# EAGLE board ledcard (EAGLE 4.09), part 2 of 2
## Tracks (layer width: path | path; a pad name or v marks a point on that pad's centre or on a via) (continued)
B$I.25  (via drill 0.2) (continued)
  Bottom 0.2: 95.08,25.39 79.29,25.39 | v95.08,25.41 95.08,25.39 | 95.08,25.39 95.12,25.39 | 58.66,26.21 52.28,32.59 52.28,32.96 52.23,33.01 49.93,33.01 49.93,32.98 v49.91,32.96
B$I.26  (via drill 0.2)
  Top 0.15: U.Y.P$P5 30.23,58.17 30.23,59.59 30.76,60.11 30.75,60.11 | U.X1.P$P5 34.35,18.01 34.35,19.18 33.53,19.99 v33.58,40.55 | U.X2.P$P5 101.53,17.99 101.53,18.79 101.19,18.79 96.64,23.29 94.7,23.29 94.43,23.56 v94.37,23.56 | 30.75,60.11 30.74,60.1 | 30.75,60.11 30.79,60.15 v32.71,60.15 33.26,60.15 36.24,57.43 36.23,57.19 45.03,48.39 v45.03,47.18 v45.02,47.18
  Top 0.2: v76.88,23.59 76.41,24.06 76.41,27.61 76.42,27.63 U2.24 | v56.83,44.86 56.83,42.88 56.49,42.54 56.49,40.51 v54.7,38.72 | v54.7,38.72 v54.69,38.71 | v54.7,38.73 v54.7,38.72 | v76.87,30.97 76.43,30.53 76.43,28.82 | U2.24 76.42,28.91 | U2.24 76.43,28.82 | 76.43,28.82 76.43,28.61
  Bottom 0.15: v33.58,40.55 33.73,40.76 33.73,45.51 | 32.7,60.15 32.69,60.15 | v32.71,60.15 32.7,60.15 | 33.63,59.34 33.51,59.34 32.7,60.15 | v54.69,38.72 54.81,38.72 58.23,35.3 58.72,35.3 58.74,35.32 58.75,35.32 | 33.63,45.76 33.63,51.12 33.64,51.12 34.92,52.4 34.92,54.32 33.74,55.5 33.74,56.25 33.68,56.31 33.68,59.18 v32.72,60.14 | 94.37,23.59 94.38,23.58 v94.38,23.57 v94.37,23.56 | 47.14,44.78 46.8,45.13 46.8,45.75 45.37,47.18 v45.03,47.18 v45.02,47.18
  Bottom 0.17: 33.63,45.76 33.73,45.51 | v54.69,38.72 v54.7,38.73
  Bottom 0.2: 94.37,23.59 v76.88,23.59 | 47.14,44.78 56.73,44.76 v56.83,44.86 | 58.75,35.32 58.99,35.56 62.01,35.56 62.12,35.45 65.53,35.45 70.1,30.88 76.79,30.88 v76.87,30.96 v76.87,30.97 | v32.72,60.14 32.72,60.13 v32.71,60.15
B$I.27  (via drill 0.2)
  Top 0.15: v34.15,39.91 33.93,39.94 | U.X2.P$P6 101.93,18.81 97.1,23.64 95.19,23.64 94.95,23.89 | 34.08,39.91 33.96,39.79 33.96,20.02 34.76,19.22 34.76,18.41 | 52.48,37.91 52.48,37.92 52.47,37.91 | 52.48,37.91 v52.47,37.9 | 79.68,26.94 79.68,26.92 80.13,26.47 81.17,26.47 | 52.48,37.91 52.47,37.91 | 52.47,37.91 v52.45,37.89 | 52.48,37.9 52.48,37.89 | 52.48,37.9 52.48,37.91 | 52.48,37.9 52.47,37.91 | 52.48,37.91 52.45,37.91 52.44,37.9 52.45,37.9 | 52.45,37.9 52.48,37.9 | U.Y.P$P6 31.1,58.24 31.63,58.24 | 31.63,58.24 31.62,58.25 31.76,58.39 v34.27,58.39 | 31.63,58.24 31.65,58.24 | v52.46,37.89 v52.45,37.88 52.43,37.88 52.45,37.9
  Top 0.17: v34.15,39.91 34.08,39.91 34.81,39.91 35.01,39.71 46.11,39.71 47.88,37.94 52.46,37.94 52.48,37.92 | U.Y.P$P6 | 55.96,45.51 61.03,45.51 62.29,44 69.5,44 70.83,45.33 70.85,45.31 71.31,45.31 | 52.48,37.92 52.48,37.91 | 52.48,37.92 52.46,37.92
  Top 0.2: U2.64 72.92,43.69 71.31,45.31 | 55.96,45.51 55.93,45.26 55.93,41.47 52.36,37.9 | 94.95,23.89 92.33,26.47 81.17,26.47 | 79.68,26.94 79.68,27.41 v79.51,27.59 | 52.36,37.9 52.35,37.89 | 52.46,37.92 52.36,37.9 | U.X1.P$P6 34.76,18.41
  Bottom 0.15: v34.15,39.91 34.16,40.11 34.16,48.21 34.11,48.26 34.11,51.01 34.12,51.01 35.23,52.12 35.23,54.5 34.08,55.65 34.08,58.2 v34.27,58.39 | 64.41,29.19 63.52,29.19 54.77,37.93 52.5,37.93 52.48,37.91 | 52.48,37.91 v52.46,37.89 | 52.48,37.91 52.48,37.92
  Bottom 0.2: v79.51,27.59 77.76,29.34 64.53,29.31 64.41,29.19
B$I.28  (via drill 0.2, 0.3)
  Top 0.15: U.X1.P$R5 33.56,17.99 33.56,18.89 32.53,19.91 v32.51,41.96 | 29.43,58.95 U.Y.P$R5 29.43,58.97 29.43,60.56 30.21,61.34 v31.04,61.34 | v32.51,41.96 v32.51,41.98 | U.X2.P$R5 100.74,17.99 99.43,17.99 97.88,19.54 | 56.18,38.95 v54.06,36.83 v54.05,36.83 | 33.73,42.11 32.59,42.11 v32.51,41.96
  Top 0.17: v51.31,39.44 50.56,38.69 48.31,38.69 46.58,40.41 35.43,40.41 33.73,42.11
  Top 0.2: 97.88,19.54 97.73,19.69 72.83,19.69 | v60.33,29.09 61.03,28.39 61.03,27.71 69.06,19.69 72.83,19.69 | 72.83,19.69 72.71,19.69 | 56.18,38.95 57.13,39.9 v57.13,42.12 | U2.60 74.93,41.61 v75.53,42.14
  Bottom 0.15: v60.33,29.09 60.33,31.71 55.21,36.83 v54.05,36.83 | v32.51,41.98 32.53,41.91 32.76,42.14 32.91,42.1 32.91,51.41 32.91,51.4 32.92,51.4 32.92,51.56 34.25,52.89 34.25,54.06 32.94,55.37 32.94,55.62 31.38,57.18 31.38,57.39 | 52.31,42.2 52.31,42.26 56.99,42.26 v57.13,42.12
  Bottom 0.17: v31.04,61.34 31.38,60.84 31.38,57.39
  Bottom 0.2: v51.31,39.44 52.31,42.2 75.53,42.22 v75.53,42.14
B$I.29  (via drill 0.2)
  Top 0.15: U.X1.P$R6 33.96,19.08 33.01,20.04 33.01,41.41 33.03,41.39 v33.13,41.49 33.81,41.49 | U.X2.P$R6 100.95,18.39 100.28,19.06 100.07,19.06 96.23,22.9 94.03,22.9 94.03,22.91 94.04,22.91
  Top 0.17: 51.53,38.36 48.03,38.36 46.36,40.04 35.26,40.04 33.81,41.49 | U.Y.P$R6 v32.73,59.15
  Top 0.2: v92.51,24.44 94.04,22.91 | 51.53,38.36 51.95,38.36 54.96,41.37 54.96,45.26 55.79,46.09 61.14,46.09 62.74,44.49 69,44.49 69.57,45.06 v69.58,45.1 | v77.29,44.39 76.92,44.18 U2.56 | U2.56 76.93,40.43 | v76.93,38.52 U2.56
  Bottom 0.15: 33.26,41.66 33.13,41.53 v33.13,41.49 | 33.26,58.24 33.26,56.12 33.39,55.98 33.39,55.42 34.58,54.23 34.58,52.61 33.27,51.3 33.27,51.29 33.26,51.29 33.26,50.2 33.25,50.19 33.26,50.19
  Bottom 0.17: 33.26,41.66 33.26,50.19
  Bottom 0.2: v92.51,24.44 97.21,24.44 98.53,25.76 98.53,27.16 93.65,32.03 93.62,32.05 93.62,32.06 83.37,32.06 v76.93,38.52 | v69.58,45.1 71.1,45.1 71.74,44.32 77.28,44.32 v77.29,44.39 | v32.73,59.15 32.98,58.51 33.26,58.24
B$I.30  (via drill 0.2)
  Top 0.15: U.Y.P$T6 31.92,59.36 | U.X1.P$T6 31.96,19.59 31.96,40.66 31.93,40.64 31.91,40.66 31.93,40.66 31.94,40.72 | 32.83,43.21 32.82,43.2 32.63,43.2 v31.99,43.84 | v96.21,22.1 v96.22,22.1 99.92,18.39 U.X2.P$T6
  Top 0.17: v50.26,39.34 48.36,39.34 46.86,40.84 35.73,40.84 33.36,43.21 32.83,43.21 31.94,42.27 31.94,40.72 | v31.94,59.59 31.92,59.36
  Top 0.2: v78.41,38.34 78.68,38.6 78.68,38.89 78.91,39.1 78.92,39.11 U2.52 | v78.78,43.76 v78.77,43.75 78.78,43.74 78.78,43.73 78.92,43.59 U2.52 | U2.52
  Bottom 0.15: 32.57,55.51 32.57,55.3 33.93,53.83 33.93,53.03 31.99,51.13 v31.99,43.84
  Bottom 0.17: 32.57,55.51 30.91,57.19 30.91,60.68 30.18,61.41 30.18,61.81 30.33,61.96 31.38,61.96 31.83,61.51 31.83,60.01 v31.94,59.59
  Bottom 0.2: v78.78,43.76 78.58,42.64 78.16,42.21 76.71,42.21 76.11,42.81 51.63,42.79 v50.26,39.34 | v96.22,22.1 99.18,25.06 99.18,27.29 93.86,32.61 84.05,32.61 78.89,37.77 78.91,37.79 v78.41,38.34
B$I.31  (via drill 0.2)
  Top 0.15: U.X1.P$T5 31.36,19.39 v31.36,31.99 v31.36,41.14 | U.Y.P$T5 29.81,59.37 29.81,60.14 30.18,60.59 v30.19,60.56 | U.X2.P$T5 98.95,17.59 v98.28,18.26 | 39.41,31.76 39.09,31.76 v38.84,31.51
  Top 0.17: v50.78,31.76 39.41,31.76
  Top 0.2: 74.42,24.79 U2.20 | v74.42,24.08 74.42,24.79 | 74.42,24.79 74.43,24.79 74.43,24.16
  Bottom 0.15: 37.58,30.54 37.58,30.55 37.57,30.55 38.53,31.51 v38.84,31.51 | 30.18,55.71 31.9,53.99 33.35,53.99 33.35,53.98 33.61,53.72 33.61,53.16 33.1,52.65 32.15,52.64 31.41,51.92 31.43,51.91
  Bottom 0.17: v31.36,41.14 31.43,51.91 | 30.18,55.71 v30.19,60.56 | 37.58,30.54 32.76,30.54 31.62,31.68
  Bottom 0.2: v50.78,31.76 58.13,24.56 74.08,24.56 74.43,24.21 74.43,24.07 | 31.62,31.68 31.38,31.94 31.34,31.97 v31.36,31.99 | v98.28,18.26 97.38,18.26 94.24,21.4 75.24,21.4 74.43,22.21 74.43,24.07 | 74.43,24.07 v74.42,24.08
B$USB.D+  (via drill 0.2)
  Top 0.17: U3.P$4 91.18,53.54 92.28,53.54 v92.51,53.31
  Top 0.2: K1.P$D- 126.5,88.75 v96.33,58.59
  Bottom 0.17: v96.33,58.59 92.51,54.76 v92.51,53.31
B$USB.D-  (via drill 0.2)
  Top 0.17: U3.P$5 93.15,54.01 v93.21,53.96
  Top 0.2: K1.P$D+ 124.46,84.94 v97.86,58.34
  Bottom 0.17: v93.21,53.96 93.21,54.26 96.76,57.81 97.33,57.81 v97.86,58.34
B$USB.VBUS
  Top 0.17: U3.P$7 91.16,55.76 91.88,55.76 U3.P$8 91.94,55.76 91.94,56.59 93.16,57.81 93.16,59.29 93.21,59.34 91.86,60.69 91.91,60.74 U1.1 93.38,62.26 93.38,63.71 C2.P | 147.18,92.44 147.18,92.47 K1.P$VCC
  Top 0.2: C2.P 122.05,92.44 147.18,92.44
B$X.I.CP  (via drill 0.2)
  Top 0.15: 58.48,25.25 58.48,25.26 | 58.48,25.24 58.48,14.41 | v39.83,12.3 v39.83,12.31 39.81,12.32 39.96,12.47 39.96,16.31 39.59,16.68 39.59,16.79 U.X1.P$H4 39.55,16.78 U.X1.P$J4 | U.X1.P$A4 45.16,16.77 45.6,16.34 v46.13,16.34
  Top 0.2: 58.48,14.41 v55.93,11.75 | v46.13,16.34 46.18,16.29 46.18,16.26 | U.X1.P$T4 33.15,16.8 32.32,16.8 v32.31,16.81 | v75.37,25.19 75.36,25.19 75.33,25.22 75.42,25.31 U2.22 | 58.48,25.24 58.48,25.25 58.48,25.19 v58.51,25.16
  Bottom 0.15: 46.16,16.31 43.36,16.31 v39.83,12.3 39.83,12.74 | v58.51,25.16 75.35,25.19 75.35,25.18 | 75.35,25.18 75.34,25.17 | v75.37,25.19 75.35,25.18 | 39.83,12.74 39.84,12.72 | 35.88,13.24 39.33,13.24 39.83,12.74 | v55.93,11.75 v55.93,11.76 55.26,11.09
  Bottom 0.2: 35.88,13.24 v32.31,16.81 | 46.16,16.31 51.38,11.09 55.26,11.09 | 46.16,16.31 v46.13,16.34 | 46.16,16.31 46.18,16.29 46.18,16.26
B$X.I.CP.1  (via drill 0.2)
  Top 0.15: U.X2.P$A4 v113.41,17.09 | v99.61,16.75 U.X2.P$T4 | 77.76,24.86 77.76,24.79 89.57,24.79 | 107.16,13.71 107.12,13.78 107.12,16.6 106.93,16.6 U.X2.P$H4 106.72,16.78 105.92,16.78 | 105.92,16.78 105.9,16.78 | 105.92,16.78 U.X2.P$J4
  Top 0.2: U2.26 77.42,25.95 77.42,25.4 77.42,25.17 77.76,24.86 | v93.92,20.49 89.57,24.79 | 107.16,13.69 107.16,13.71 | 107.16,13.69 107.16,13.66 107.16,13.65 | 107.16,13.64 v107.16,12.29 | 107.16,13.64 107.16,13.69 | 107.16,13.64 107.14,13.62
  Bottom 0.15: 99.61,16.74 99.6,16.73 | v99.61,16.76 99.61,16.74 | v99.61,16.75 99.64,16.77 99.61,16.74 | 107.18,13.67 107.18,13.69 107.17,13.7 108.56,15.09 | 108.56,15.11 108.56,15.09 | 105.53,15.31 108.38,15.31 108.6,15.09 | 108.6,15.09 108.58,15.09 | 108.6,15.09 108.5,15.19 108.47,15.19 108.47,15.18 108.56,15.09
  Bottom 0.2: 98.83,16.76 v99.61,16.76 | 98.83,16.76 98.26,16.19 98.26,15.74 98.68,15.31 105.53,15.31 | v93.92,20.49 93.91,20.49 93.9,20.48 97.62,16.76 98.83,16.76 | 107.18,13.67 107.16,13.69 | 107.16,13.69 v107.16,12.29 107.16,13.62 | 107.16,13.62 107.17,13.61 | 107.16,13.69 107.16,13.63 107.16,13.62 | v113.41,17.09 113.73,16.76 113.73,16.66 113.88,16.51 113.88,15.31 113.68,15.11 108.56,15.11
B$X.O.0
  Top 0.15: U.X1.P$A2 45.95,15.19 52.21,8.93 68.01,8.93 74.71,2.23 | X.0.P$ 74.71,2.23 | 74.71,2.23 74.72,2.23
B$X.O.1
  Top 0.15: U.X1.P$A1 52.08,7.44 64.87,7.44 70.08,2.26 70.07,2.25 X.1.P$
B$X.O.2
  Top 0.15: U.X1.P$B2 44.76,14.79 45.53,14.79 52.05,8.27 66.5,8.27 72.46,2.31 72.41,2.26 72.38,2.26 72.37,2.25 X.2.P$
B$X.O.3
  Top 0.15: U.X1.P$B1 51.89,6.86 63.11,6.86 67.78,2.19 X.3.P$
B$X.O.4
  Top 0.15: U.X1.P$C2 43.96,14.79 43.96,14 51.85,6.14 61.66,6.14 65.5,2.29 | X.4.P$ 65.48,2.29 65.5,2.29 | 65.5,2.29 65.51,2.27
B$X.O.5
  Top 0.15: U.X1.P$C1 43.56,13.89 51.89,5.49 59.91,5.49 X.5.P$ | X.5.P$ 63.21,2.21 | X.5.P$ | X.5.P$ | X.5.P$
B$X.O.6
  Top 0.15: U.X1.P$D2 43.16,14.79 43.16,13.79 52.02,4.92 58.23,4.92 60.93,2.23 60.93,2.22 | 60.93,2.22 60.93,2.21 | X.6.P$ 60.93,2.22
B$X.O.7
  Top 0.15: U.X1.P$D1 42.76,13.59 52.1,4.24 56.6,4.24 X.7.P$ | X.7.P$ 58.59,2.22 X.7.P$ | X.7.P$ 58.63,2.21
B$X.O.8
  Top 0.15: U.X1.P$J2 38.36,14.79 38.36,13.14 35.66,10.44 X.8.P$
B$X.O.9
  Top 0.15: X.9.P$ 37.98,2.21 37.98,12.24 38.76,13.01 U.X1.P$J1 | U.X1.P$J1 | U.X1.P$J1
B$X.O.10
  Top 0.15: U.X1.P$K2 37.56,14.79 37.56,13.31 31.16,6.91 31.16,2.29 X.10.P$
B$X.O.11
  Top 0.15: U.X1.P$K1 37.96,13.26 33.38,8.69 33.38,2.24 X.11.P$
B$X.O.12
  Top 0.15: U.X1.P$L2 36.75,14.79 36.75,13.54 26.53,3.32 26.53,2.16 26.51,2.14 26.53,2.11 | 26.53,2.11 26.56,2.09 | 26.53,2.11 X.12.P$
B$X.O.13
  Top 0.15: X.13.P$ 28.89,2.22 28.93,2.26 28.78,2.41 28.77,2.4 | U.X1.P$L1 37.16,13.38 28.77,4.99 28.77,2.4 | 28.77,2.4 28.77,2.26
B$X.O.14
  Top 0.15: U.X1.P$M2 35.96,14.79 35.96,13.74 33.33,11.11 29.22,11.11 | X.14.P$ 22.01,2.24 22.01,3.89 29.22,11.09 29.22,11.11 | 29.22,11.11 29.22,11.12
B$X.O.15
  Top 0.15: X.15.P$ 24.22,2.24 24.16,2.31 24.18,2.34 24.18,3.85 | U.X1.P$M1 36.36,13.65 32.83,10.12 30.38,10.12 24.18,3.92 24.18,3.85 | 24.18,3.85 24.18,3.91
B$X.O.16
  Top 0.15: U.X1.P$E2 42.36,14.79 42.36,13.33 51.9,3.79 54.75,3.79 56.29,2.24 56.29,2.23 X.16.P$
B$X.O.17
  Top 0.15: U.X1.P$E1 41.96,13.11 52.11,3.07 53.18,3.07 54.01,2.24 X.17.P$
B$X.O.18
  Top 0.15: U.X1.P$F2 41.56,14.79 41.56,12.56 51.73,2.38 51.73,2.21 | 51.73,2.21 51.73,2.19 | 51.73,2.21 X.18.P$
B$X.O.19
  Top 0.15: U.X1.P$F1 41.16,13.61 41.16,12.01 49.41,3.7 49.41,2.25 49.45,2.26 X.19.P$
B$X.O.20
  Top 0.15: U.X1.P$G2 40.76,14.79 40.76,11.17 47.13,4.79 47.13,2.21 X.20.P$
B$X.O.21
  Top 0.15: X.21.P$ 44.86,2.21 44.86,5.74 44.87,5.72 | U.X1.P$G1 40.42,14.33 40.42,10.89 44.87,6.44 44.87,5.72 | 44.87,5.72 44.87,5.68
B$X.O.22
  Top 0.15: U.X1.P$H1 39.56,12.88 39.07,12.39 39.07,9.65 42.39,6.33 42.51,6.33 42.51,6.34 42.53,6.36 X.22.P$
B$X.O.23
  Top 0.15: X.23.P$ 40.26,2.26 38.31,4.21 38.31,12.13 39.09,12.91 39.09,12.98 39.14,12.98 39.15,12.97 39.15,14.78 U.X1.P$H2
B$X.O.24
  Top 0.15: U.X1.P$N2 35.16,14.79 35.16,13.84 33.56,12.24 27.48,12.24 | X.24.P$ 17.45,2.22 17.46,2.21 27.48,12.26 27.48,12.24 | 27.48,12.24 27.51,12.25
B$X.O.25
  Top 0.15: X.25.P$ 19.63,2.26 29.09,11.71 | U.X1.P$N1 35.56,13.79 33.5,11.72 29.09,11.71 | 29.11,11.69 29.07,11.65 29.09,11.71
B$X.O.26
  Top 0.15: U.X1.P$P2 34.36,14.79 34.36,14.09 33.63,13.36 24.04,13.36 X.26.P$ | X.26.P$ | 12.92,2.22 X.26.P$ | 12.92,2.22 X.26.P$ | 12.92,2.22
B$X.O.27
  Top 0.15: U.X1.P$P1 34.76,13.88 33.54,12.66 25.57,12.66 X.27.P$ | X.27.P$ | X.27.P$
B$X.O.28
  Top 0.15: X.28.P$ 8.11,4.31 10.58,4.31 21.06,14.79 21.07,14.78 | 21.07,14.78 21.02,14.77 | U.X1.P$R2 33.57,14.78 21.07,14.78
B$X.O.29
  Top 0.15: U.X1.P$R1 33.48,13.91 22.23,13.91 X.29.P$ | X.29.P$ 10.55,2.14 | X.29.P$
B$X.O.30
  Top 0.15: U.X1.P$T1 21.6,14.39 | 21.6,14.39 21.58,14.41 | 21.6,14.39 10.8,3.59 9.63,3.59 8.36,2.31 8.18,2.31 | 8.18,2.31 8.13,2.31 | 8.18,2.31 X.30.P$
B$X.O.31
  Top 0.15: U.X1.P$T2 19.61,15.19 9.43,5.01 6.36,5.01 3.71,2.36 3.72,2.35 X.31.P$
B$X.O.32
  Top 0.15: X.32.P$ 132.8,15.19 U.X2.P$A2
B$X.O.33
  Top 0.15: 131.37,14.39 U.X2.P$A1
  Top 0.2: X.33.P$ 141.23,2.21 141.23,4.54 131.37,14.39
B$X.O.34
  Top 0.15: U.X2.P$B2 111.94,15.59 134.75,15.59 X.34.P$
B$X.O.35
  Top 0.15: X.35.P$ 138.95,2.16 138.96,2.16 138.96,3.24 131.61,10.59 116.53,10.59 116.57,10.55 | U.X2.P$B1 112.07,13.85 113.2,13.85 116.5,10.55 116.57,10.55 | 116.57,10.55 116.59,10.55
B$X.O.36
  Top 0.15: U.X2.P$C2 111.14,14.79 131.93,14.81 143.41,3.34 143.41,2.26 143.44,2.26 X.36.P$
B$X.O.37
  Top 0.15: X.37.P$ 136.52,2.29 136.51,2.29 136.51,2.86 129.21,10.16 116.02,10.16 115.98,10.2 115.96,10.2 115.96,10.64 113.08,13.53 111.6,13.53 U.X2.P$C1
B$X.O.38
  Top 0.15: U.X2.P$D2 110.33,14.81 110.33,14.03 111.18,13.17 112.87,13.17 115.63,10.41 115.63,10.06 115.98,9.71 115.98,9.6 116,9.59 126.98,9.59 134.26,2.31 134.26,2.18 | 134.26,2.18 134.26,2.16 | X.38.P$ 134.26,2.18
B$X.O.39
  Top 0.15: U.X2.P$D1 109.93,13.96 111.07,12.82 112.64,12.82 115.28,10.18 115.28,9.85 115.63,9.5 115.63,9.26 115.96,8.94 116.27,8.94 | X.39.P$ 132.03,2.24 125.33,8.94 116.27,8.94 | 116.27,8.94 116.31,8.94 | 116.27,8.94
B$X.O.40
  Top 0.15: U.X2.P$J2 105.53,14.79 105.53,12.7 104.44,11.61 104.44,7.81 105.54,6.71 105.54,5.89 105.49,5.84 105.53,5.8 105.53,5.76 | 109.05,2.25 X.40.P$
  Top 0.2: 105.53,5.76 109.05,2.25
B$X.O.41
  Top 0.15: U.X2.P$J1 105.93,12.63 104.86,11.56 104.86,8 109.43,3.43 110.15,3.43 111.3,2.29 111.39,2.29 111.39,2.25 X.41.P$
B$X.O.42
  Top 0.15: U.X2.P$K2 104.73,14.79 104.73,12.88 103.5,11.65 103.5,7.2 104.47,6.24 104.48,6.24 | 104.48,2.26 104.48,2.25 104.5,2.23 104.49,2.22 X.42.P$
  Top 0.2: 104.48,6.24 104.48,2.26
B$X.O.43
  Top 0.15: 106.78,2.26 106.77,2.25 X.43.P$ | 105.14,3.9 105.14,6.45 104.02,7.58 104.04,7.58 | U.X2.P$K1 105.13,12.81 104.02,11.7 104.02,7.6 104.04,7.58 | 104.04,7.58 104.06,7.55
  Top 0.2: 105.13,3.91 105.14,3.9 106.78,2.26
B$X.O.44
  Top 0.15: U.X2.P$L2 103.93,14.79 103.93,13.11 99.9,9.08 99.9,2.21 99.89,2.21 | X.44.P$ | X.44.P$ | 99.89,2.21 99.87,2.19 | 99.89,2.21 X.44.P$
B$X.O.45
  Top 0.15: 102.21,2.34 102.21,2.33 102.17,2.29 X.45.P$ | U.X2.P$L1 104.33,12.95 102.21,10.83 102.21,5.89 102.21,5.88 | 102.21,5.88 102.19,5.87 | 102.21,5.88 102.21,5.89
  Top 0.2: 102.21,5.89 102.21,2.34
B$X.O.46
  Top 0.15: U.X2.P$M2 103.13,14.79 103.13,13.46 95.31,5.63 95.31,2.99 95.33,3.01 95.33,3.04 | 95.33,2.25 95.28,2.25 95.27,2.24 95.29,2.22 X.46.P$
  Top 0.2: 95.33,3.04 95.33,2.25
B$X.O.47
  Top 0.15: X.47.P$ | U.X2.P$M1 103.53,13.3 97.58,7.34 97.58,3.78 97.53,3.74 97.58,3.69 | 97.58,3.69
  Top 0.2: 97.58,3.69 X.47.P$
B$X.O.48
  Top 0.15: U.X2.P$E2 109.53,14.79 109.53,13.47 110.67,12.33 112.31,12.33 115.3,9.33 115.3,9.01 116.17,8.14 116.24,8.14 116.17,8.21 116.15,8.21 | X.48.P$ 129.8,2.23 129.81,2.24 123.91,8.14 116.23,8.14 116.15,8.21 | 116.15,8.21 116.1,8.21
B$X.O.49
  Top 0.15: X.49.P$ 127.43,2.29 122.08,7.64 116.16,7.61 116.17,7.6 | U.X2.P$E1 109.13,13.4 110.55,11.98 112.17,11.98 114.91,9.24 114.91,8.8 116.03,7.67 116.03,7.6 116.17,7.6 | 116.17,7.6 116.26,7.6
B$X.O.50
  Top 0.15: U.X2.P$F2 108.73,14.79 108.73,13.29 110.44,11.58 111.77,11.58 114.56,8.8 114.56,8.44 116.64,6.36 121.14,6.36 125.16,2.33 125.13,2.3 X.50.P$
B$X.O.51
  Top 0.15: U.X2.P$F1 108.36,14.37 108.36,13.12 110.27,11.21 111.51,11.21 114.23,8.49 114.23,8.12 117.83,4.51 117.88,4.51 | X.51.P$ 122.86,2.26 120.56,4.56 120.55,4.55 120.55,4.51 117.88,4.51 | 117.88,4.51 117.83,4.51
B$X.O.52
  Top 0.15: X.52.P$ 120.54,2.24 120.55,2.23 | U.X2.P$G2 107.53,15.17 107.92,14.8 107.92,14.21 108.04,14.07 108.04,12.97 110.11,10.9 110.97,10.9 111.58,10.29 111.58,10.22 116.99,4.81 116.99,4.74 117.95,3.78 117.98,3.81 120.01,3.81 120.55,3.27 120.55,2.23 | 120.55,2.23 X.52.P$
B$X.O.53
  Top 0.15: 118.24,2.25 X.53.P$ | U.X2.P$G1 107.53,14.12 107.68,13.96 107.68,12.79 118.22,2.25 118.24,2.25 | 118.26,2.24 118.25,2.24 118.24,2.25
B$X.O.54
  Top 0.15: U.X2.P$H1 106.64,14.33 106.64,12.43 105.73,11.51 105.73,8.3 109.61,4.42 113.76,4.42 115.94,2.24 115.63,2.24 | 115.91,2.24 X.54.P$
  Top 0.2: 115.63,2.24 115.91,2.24
B$X.O.55
  Top 0.15: U.X2.P$H2 106.33,14.79 106.33,12.56 105.28,11.51 105.28,8.19 109.52,3.95 112.03,3.95 113.65,2.32 X.55.P$ | X.55.P$ 113.68,2.19 | X.55.P$
B$X.O.56
  Top 0.15: U.X2.P$N2 102.33,14.79 102.33,13.88 101.28,12.82 101.28,12.8 100.11,11.63 100.11,11.61 | 90.73,2.24 X.56.P$
  Top 0.2: 100.11,11.61 90.73,2.24
B$X.O.57
  Top 0.15: X.57.P$ 92.96,2.26 93.01,2.26 93.01,3.95 102.73,13.67 U.X2.P$N1
B$X.O.58
  Top 0.15: U.X2.P$P2 101.53,14.79 101.53,14.06 101,13.53 97.46,13.53 97.07,13.14 | X.58.P$ | 97.07,13.14 97.04,13.1 | 97.07,13.14 97.08,13.14
  Top 0.2: 97.08,13.14 X.58.P$
B$X.O.59
  Top 0.15: 88.38,2.26 X.59.P$ | U.X2.P$P1 101.93,13.95 101.16,13.17 99.33,13.17 98.89,12.74 98.88,12.74
  Top 0.2: 98.88,12.74 88.38,2.26
B$X.O.60
  Top 0.15: U.X2.P$R2 100.73,14.79 100.66,14.8 91.78,14.81 | X.60.P$ 79.27,2.22 79.27,2.23 79.23,2.26
  Top 0.2: 91.78,14.81 79.23,2.26
B$X.O.61
  Top 0.15: 83.73,2.24 83.75,2.21 X.61.P$ | U.X2.P$R1 101.13,14.22 100.81,13.9 95.45,13.9 95.26,13.71 | 95.26,13.71 95.19,13.64 | 95.26,13.71
  Top 0.2: 95.26,13.71 83.73,2.24
B$X.O.62
  Top 0.15: 81.55,2.25 X.62.P$ | U.X2.P$T1 93.69,14.39
  Top 0.2: 93.69,14.39 81.55,2.25
B$X.O.63
  Top 0.15: U.X2.P$T2 100.4,15.24 | 76.93,2.24 X.63.P$
  Top 0.2: 100.4,15.24 89.95,15.23 76.93,2.24
B$Y.I.CP  (via drill 0.2)
  Top 0.15: 29.03,53.75 U.Y.P$J4 U.Y.P$H4 29.42,53.36 31.2,53.36 | U.Y.P$A4 29.03,47.35 29.03,46.71 29.05,46.69 29.05,46.66 v29.06,46.66 v29.07,46.67 | U.Y.P$T4 29.02,60.3 v29.03,60.91 | 31.2,53.36 31.76,53.36 | v33.03,53.36 31.2,53.36
  Top 0.17: v51.61,32.41 39.83,32.41 v38.58,33.69
  Top 0.2: U2.27 77.92,25.68 v78.3,25.43
  Bottom 0.15: v38.58,33.69 38.48,33.51 | 31.76,53.36 v33.03,53.36 | 29.43,46.66 29.42,46.67 v29.07,46.67 29.03,46.71
  Bottom 0.2: 29.03,46.71 29.03,50.96 31.76,53.36 29.03,55.76 v29.03,60.91 | v51.61,32.41 58.26,25.81 58.96,25.81 58.96,25.76 77.97,25.76 v78.3,25.43 | 38.48,33.51 37.36,32.39 30.41,39.34 30.41,45.69 29.43,46.66
B$Y.O.0
  Top 0.15: 9.19,6.46 9.18,6.46 | 9.19,6.46 27.38,24.66 27.38,47.36 U.Y.P$A2 | R.0.P$1 9.19,6.46 | R.0.P$1 | R.0.P$1
B$Y.O.1
  Top 0.15: U.Y.P$A1 26.62,30.1 9.16,12.64 9.17,12.63 9.18,12.63 9.19,12.64 R.1.P$1
B$Y.O.2
  Top 0.15: U.Y.P$B2 27.02,47.76 27.02,27.22 9.33,9.54 9.14,9.54 | 9.14,9.54 9.13,9.54 | R.2.P$1 9.14,9.54
B$Y.O.3
  Top 0.15: U.Y.P$B1 26.48,48.16 25.83,47.51 25.83,32.44 9.2,15.8 R.3.P$1
B$Y.O.4
  Top 0.15: U.Y.P$C2 27.1,48.59 27.07,48.56 25.77,48.56 24.78,47.57 24.78,34.34 R.4.P$1
B$Y.O.5
  Top 0.15: U.Y.P$C1 25.28,48.96 23.81,47.49 23.81,36.61 9.21,22.01 9.16,22.01 9.16,21.98 R.5.P$1
B$Y.O.6
  Top 0.15: U.Y.P$D2 27,50.16 23.06,50.16 22.38,49.46 22.38,41.36 9.18,28.16
  Top 0.2: R.6.P$1 9.18,28.12 9.18,28.16
B$Y.O.7
  Top 0.15: U.Y.P$D1 23.78,49.76 23.08,49.06 23.08,38.96 9.18,25.06 R.7.P$1
B$Y.O.8
  Top 0.15: U.Y.P$J2 27.02,54.16 18.18,54.16 13.28,59.06 R.8.P$1 | R.8.P$1 9.18,59.06 | R.8.P$1
B$Y.O.9
  Top 0.15: U.Y.P$J1 17.48,53.76 15.28,55.96 9.18,55.96 R.9.P$1
B$Y.O.10
  Top 0.15: U.Y.P$K2 27.02,54.96 19.58,54.96 9.48,65.06 9.28,65.06 9.28,65.16 9.22,65.22 R.10.P$1
B$Y.O.11
  Top 0.15: U.Y.P$K1 26.52,54.56 18.88,54.56 11.18,62.26 9.11,62.26 | 9.11,62.26 9.08,62.26 | 9.11,62.26 R.11.P$1
B$Y.O.12
  Top 0.15: U.Y.P$L2 27.02,55.76 20.98,55.76 20.28,56.46 20.28,60.26 9.18,71.36 9.19,71.37 R.12.P$1
B$Y.O.13
  Top 0.15: U.Y.P$L1 20.28,55.36 19.58,56.06 19.58,58.06 9.2,68.44 | 9.2,68.44 9.18,68.46 | 9.2,68.44 R.13.P$1
B$Y.O.14
  Top 0.15: U.Y.P$M2 27.02,56.56 22.38,56.56 21.68,57.26 21.68,65.16 9.19,77.66 | 9.19,77.66 9.18,77.66 | R.14.P$1 9.19,77.66
B$Y.O.15
  Top 0.15: U.Y.P$M1 21.68,56.16 20.98,56.86 20.98,62.76 R.15.P$1 | R.15.P$1 | R.15.P$1
B$Y.O.16
  Top 0.15: U.Y.P$E2 26.99,50.97 21.65,50.97 20.98,50.26 20.98,46.06 9.19,34.26 | 9.19,34.26 9.18,34.26 | 9.19,34.26 R.16.P$1
B$Y.O.17
  Top 0.15: U.Y.P$E1 22.38,50.56 21.68,49.86 21.68,43.66 9.22,31.19 | 9.22,31.19 9.18,31.16 | 9.22,31.19 R.17.P$1
B$Y.O.18
  Top 0.15: U.Y.P$F2 27.01,51.76 20.29,51.77 9.28,40.76 9.28,40.46 R.18.P$1
B$Y.O.19
  Top 0.15: U.Y.P$F1 20.98,51.36 20.08,50.46 20.08,48.26 9.28,37.46 9.18,37.46 9.28,37.36
  Top 0.2: R.19.P$1 9.21,37.38 9.23,37.36 9.28,37.36
B$Y.O.20
  Top 0.15: U.Y.P$G2 27.02,52.56 18.88,52.56 12.98,46.66 9.2,46.66 | 9.2,46.66 9.18,46.66 | 9.2,46.66 R.20.P$1
B$Y.O.21
  Top 0.15: U.Y.P$G1 19.58,52.16 10.98,43.56 9.85,43.56 | 9.85,43.56 9.18,43.56 | 9.85,43.56 R.21.P$1
B$Y.O.22
  Top 0.15: U.Y.P$H1 26.22,52.96 18.18,52.96 14.98,49.76 9.97,49.76 | 9.97,49.76 9.18,49.76 | 9.97,49.76 R.22.P$1
B$Y.O.23
  Top 0.15: U.Y.P$H2 27.02,53.36 17.48,53.36 16.78,52.66 9.18,52.66 9.18,52.87 R.23.P$1
B$Y.O.24
  Top 0.15: U.Y.P$N2 27.02,57.36 23.78,57.36 23.08,58.06 23.08,70.06 9.21,83.94 | 9.21,83.94 9.08,84.06 | R.24.P$1 9.21,83.94
B$Y.O.25
  Top 0.15: U.Y.P$N1 23.08,56.96 22.38,57.66 | 9.19,80.75 9.18,80.76 | R.25.P$1 9.19,80.75 | 9.19,80.75 22.38,67.56
  Top 0.2: 22.38,67.56 22.38,57.66
B$Y.O.26
  Top 0.15: U.Y.P$P2 27.02,58.16 25.18,58.16 24.48,58.86 24.48,74.76 9.44,89.8 R.26.P$1
B$Y.O.27
  Top 0.15: U.Y.P$P1 24.48,57.76 23.78,58.46 23.78,72.36 9.18,86.96
  Top 0.2: R.27.P$1 9.18,86.96
B$Y.O.28
  Top 0.15: U.Y.P$R2 27.02,58.96 26.18,58.96 25.88,59.26 25.88,79.46 9.08,96.26 9.1,96.28 R.28.P$1
B$Y.O.29
  Top 0.15: U.Y.P$R1 25.78,58.56 25.18,59.16 25.18,77.26 9.22,93.23 | 9.22,93.23 9.18,93.26 | R.29.P$1 9.22,93.23
B$Y.O.30
  Top 0.15: U.Y.P$T1 26.62,60.42 26.63,60.46 26.63,81.96 9.34,99.24
  Top 0.2: R.30.P$1 9.34,99.24
B$Y.O.31
  Top 0.15: U.Y.P$T2 27.42,60.42 27.43,60.46 27.43,84.36 9.21,102.53 | 9.21,102.53 9.18,102.56 | R.31.P$1 9.21,102.53
GND  (via drill 0.2, 0.3)
  Top 0.15: U.Y.P$R4 | U.Y.P$R4 | U.Y.P$R4 U.Y.P$R3 29.08,58.56 29.43,58.21 29.43,57.21 29.18,56.96 U.Y.P$N3 | U.Y.P$M4 | U.Y.P$M4 U.Y.P$M3 | 28.22,56.94 U.Y.P$M3 | 27.83,52.54 27.83,54.17 U.Y.P$K3 28.2,54.56 | 27.83,52.54 27.83,52.51 28.18,52.16 | U.Y.P$D4 29.03,50.12 | U.Y.P$E4 29.03,50.55 29.03,50.12 | U.Y.P$M3 U.Y.P$N3 | 28.98,56.96 28.98,56.91 | 28.98,56.96 U.Y.P$N4 | U.Y.P$N3 28.98,56.96 | U.Y.P$B3 28.18,48.16 28.18,48.21 27.83,48.56 27.83,49.37 U.Y.P$D3 28.23,50.55 28.21,50.55 U.Y.P$E3 | U.Y.P$B3 U.Y.P$B4 | U.Y.P$B3 27.83,47.77 27.83,47.76 | 27.83,47.76 27.83,43.26 27.9,43.19 27.9,43.16 CAP.DEC.Y.P$1 29.62,41.41 CAP.DEC.X2.P$1 | U.X2.P$R4 101.11,16.77 101.11,16.01 | 101.11,16.01 101.12,16.01 U.X2.P$R3 | 101.11,17.01 101.28,17.19 102.46,17.19 102.73,16.91 U.X2.P$N4 | 101.11,17.01 101.11,16.01 | CAP.DEC.X2.P$1 27.93,20.38 27.91,42.87 | 101.11,17.01 100.93,17.19 99.93,17.19 99.83,17.29 98.37,17.29 96.89,18.76 97.05,18.76 CAP.DEC.X1.P$1 | 67.31,35.44 C.DEC.U2.1.P$2 | 73.53,21.26 73.53,21.39 | 73.41,21.26 73.53,21.26 | 73.53,21.26 73.53,20.99 | 29.16,56.94 28.21,56.94 28.21,56.14 | 28.21,56.14 27.86,55.79 | 28.21,52.16 27.83,52.54 | 28.21,52.16 27.82,51.76 27.82,50.94 28.26,50.49 28.26,49.84 27.83,49.41 | 27.83,48.54 28.28,48.09 28.16,48.09 27.83,47.76 | 27.88,43.19 27.88,20.41 | v29.57,17.49 29.57,17.9 | v59.93,28.14 59.83,28.14 | C.U2.DEC.2.P$1 73.38,25.17 73.38,25.09 73.11,25.09 | C.DEC.U2.3.P$1 73.46,21.08 73.68,20.86 | U.X1.P$M3 36.34,16.8 | 35.57,16.49 U.X1.P$N3 35.57,16 | 36.34,16.77 U.X1.P$M4 36.39,16.78 36.79,17.2 37.65,17.2 | U.X1.P$M3 36.36,16.76 | 37.65,17.2 37.74,17.2 37.93,16.96 | U.X1.P$K4 37.97,16.87 37.98,16.88 38.27,17.19 40.16,17.19 40.36,16.95 40.35,16.95 U.X1.P$G4 40.35,16.8 40.34,16.81
  Top 0.15: 41.95,16.01 41.96,16.02 | 40.34,16.81 40.34,15.99 U.X1.P$G3 40.37,16 40.4,16 40.4,15.95 40.77,15.58 41.57,15.58 41.96,15.97 41.98,15.97 | U.X2.P$D4 109.93,15.96 | U.X2.P$D4 U.X2.P$D3 110.32,15.6 111.17,15.6 111.54,15.98 U.X2.P$B3 111.53,16.81 111.52,16.8 | 111.52,16.8 111.52,16.82 | 111.52,16.8 U.X2.P$B4 | U.X2.P$G3 107.93,15.6 108.74,15.6 U.X2.P$E3 109.12,16.01 109.11,16.01 | U.X2.P$G3 107.91,15.6 | 109.12,16.81 109.12,16.02 | 107.14,17.19 105.45,17.19 105.11,16.85 105.11,16.79 U.X2.P$K4 U.X2.P$K3 105.13,16.88 105.45,17.19 107.13,17.19 U.X2.P$G4 107.53,16.04 107.53,16.03 107.53,16.02 U.X2.P$G3 | U.X2.P$N4 U.X2.P$N3 | U.X2.P$M4 103.51,16.77 103.53,16.75 103.51,16.81 | U.X2.P$N4 U.X2.P$N3 | 102.74,15.97 U.X2.P$N3 | 103.51,16.81 103.54,16.01 | U.X2.P$N3 102.74,16.8 103.51,16.81 | 103.51,16.81 U.X2.P$M3 | 103.51,16.81 103.53,16.83 103.88,17.19 104.73,17.19 105.12,16.8 | 29.03,50.12 U.Y.P$E4 | U.Y.P$E3 28.24,50.56 28.24,50.12 29.03,50.12 | U.Y.P$E3 | U.Y.P$E3 | U.Y.P$E4 | U.Y.P$E4 | U.Y.P$E3 27.81,51.02 27.81,51.73 U.Y.P$G3 28.21,52.16 | U.Y.P$E3 | 28.2,54.56 U.Y.P$K4 28.2,54.56 27.81,54.97 27.81,55.72 28.21,56.14 | 28.2,54.56 | U.Y.P$M3 U.Y.P$M4 | 28.22,56.94 U.Y.P$N3 | U.Y.P$N3 28.22,56.94 | 28.21,52.16 U.Y.P$G3 U.Y.P$G4 | 28.21,56.14 U.Y.P$M3 | CAP.DEC.X2.P$1 | CAP.DEC.X2.P$1 31.23,18.69 32.73,17.19 33.61,17.19 33.96,16.84 34.31,17.19 35.28,17.19 35.57,16.9 35.56,16.89 U.X1.P$N4 | CAP.DEC.X2.P$1 29.61,18.67 | 29.57,17.9 29.58,17.91 | CAP.DEC.X2.P$1 29.63,17.96 29.57,17.9 | CAP.DEC.X2.P$1 29.62,18.63 | CAP.DEC.X2.P$1 | U.X1.P$G4 40.35,16.79 40.35,16.8 40.34,16.81 | U.X1.P$E4 41.96,16.01 42.76,16.01 42.76,16.03
  Top 0.15: U.X1.P$D4 42.76,16.76 | 42.76,16.03 42.76,16.76 | U.X1.P$D3 U.X1.P$D4 | U.X1.P$D3 42.76,16.03 | 42.76,16.76 42.78,16.76 42.78,16.77 | U.X1.P$D4 42.76,16.76 | U.X1.P$D3 42.75,15.99 42.75,15.98 U.X1.P$D3 | U.X1.P$B4 U.X1.P$B3 44.07,15.7 44.07,15.59 43.18,15.59 U.X1.P$D3 | U.X1.P$R4 33.95,16.79 33.96,16.78 U.X1.P$R3 | 36.36,16.76 36.76,17.2 37.65,17.2 | 37.65,17.2 37.96,16.88 | U.X1.P$K3 | U.X1.P$K3 | U.X1.P$K3 | U.X1.P$K4 U.X1.P$K3 | U.X1.P$K4 37.96,16.93 37.71,17.18 36.78,17.18 36.38,16.79 36.38,16.04 36.36,16.02 U.X1.P$M3 | U.X1.P$K3 37.95,16.01 37.96,16.02 U.X1.P$K4 | 37.97,16.01 37.97,16 U.X1.P$K3 | U.X2.P$E4 109.13,16 109.15,15.99 109.91,15.99 109.91,16.8 109.92,16.8 U.X2.P$D4 | U.X2.P$G3 U.X2.P$G4 | U.X2.P$G3 U.X2.P$G4 107.13,17.19
  Top 0.17: 77.56,23.96 77.56,21.06 76.56,20.06 74.43,20.06 73.53,20.96 73.53,20.99 | 86.13,54.44 86.13,54.46 C.DEC.U3.P$1 | C.DEC.U3.P$1 86.21,54.46 87.65,53.01 U3.P$3 91.13,52.99 v89.91,52.99 | 83.13,56.16 83.13,56.14 C4.P$1 | 83.63,58.71 83.63,58.69 U4.2 | C.DEC.U3.P$1 87.61,53.04 88.46,53.04 88.41,53.09 88.41,53.64 88.48,53.64 C3.N | v90.26,55.39 90.91,56.04 90.91,60.74 | C2.N 91.01,63.77 91.01,63.79 88.11,63.79 C1.N | 90.91,60.74 90.86,60.74 90.86,63.62 C2.N | 90.91,60.74 U1.2 | 90.86,63.84 90.95,63.74 C2.N | 59.16,52.19 59.16,47.91 | v70.67,52.19 65.68,52.21 65.66,52.19 65.66,52.14 | C.T1.C.N 79.64,53.66 79.61,53.69 79.66,53.74 79.81,53.74
  Top 0.2: T1.2 79.56,51.61 | C.T1.C.N 79.69,51.74 T1.2 | 79.68,51.64 T1.2 | 79.63,51.61 79.61,51.64 T1.2 | U2.18 73.42,28.72 73.43,28.71 C.U2.DEC.2.P$1 73.43,21.28 | C.XTAL1.P$1 59.11,47.87 59.16,47.91 59.09,47.98 C.XTAL2.P$1 | 73.43,21.28 73.46,21.32 C.DEC.U2.3.P$1 | 73.43,21.28 73.41,21.26 | U2.6 67.7,35.83 67.31,35.44 | 27.88,20.41 29.58,18.71 | v57.81,11.11 59.98,13.84 59.98,28.24 59.83,28.14 | v62.23,28.14 66.78,23.59 71.61,23.59 73.11,25.09 | 73.38,36.21 73.34,36.17 73.34,35.83 | 73.38,36.21 73.41,36.19 | 73.43,30.56 73.43,30.59 74.68,31.84 74.68,36.89 | U2.25 76.92,26 76.93,25.52 76.93,24.44 77.56,23.96 | C.T1.C.N 83.11,53.66 83.11,54.44 86.13,54.44 | C.DEC.U3.P$1 83.13,54.46 83.13,56.14 | C4.P$1 83.63,56.66 83.63,58.69 | 90.86,63.84 123.09,96.07 | v70.67,52.19 59.16,52.19 | C.DEC.U2.6.P$2 69.75,48.04 65.66,52.14 | CAP.DEC.X1.P$1 96.7,19.11 73.98,19.11 74.08,19.01 v74.08,18.86 | 75.46,40.33 75.44,40.33 | 75.46,40.33 75.53,40.26 75.54,40.27 75.54,40.3 75.45,40.3 U2.59 75.67,40.33 | 75.67,40.33 U2.58 75.67,40.33 | 75.67,40.33 75.46,40.33 | 75.67,36.89 79.92,36.89 U2.50 79.92,44.9 | 75.67,40.33 | 75.67,36.89 75.57,36.89 | 75.67,40.3 75.67,40.33 | 73.38,36.21 74.06,36.89 75.67,36.89 | 75.67,40.3 75.67,40.33 | 75.67,36.89 75.67,40.3 | 79.81,53.74 78.51,55.53 76.38,55.53 73.76,52.31 73.74,52.31 73.74,52.28 v73.76,52.26 | C2.N 90.98,63.98 92.05,65.05 B-.PP | 76.65,61.21 76.65,58.9 76.73,58.82 76.69,58.78 D1V8.P$K 76.65,55.01 76.67,54.99 78.56,54.99 79.69,53.87 C.T1.C.N | T2.2 90.26,35.38 v90.28,35.38 | U$33.N 102.58,37.33 | U$33.N 105.18,37.29 105.19,37.28 | v101,37.21 102.46,37.21 U$33.N | 105.19,37.28 105.2,37.27
  Top 0.2: 105.19,37.28 C.U5.1.P$1 104.98,37.26 U5.15 109.34,37.26 112.52,40.44 113.25,40.44 113.37,40.56 113.43,40.51 U5.7 113.49,40.87 113.67,41.05 113.57,41.16 U5.8 113.51,41.16 113.55,41.11 114.59,42.15 U$36.P | 73.68,20.86 v74.18,20.86 | 79.92,44.9 C.DEC.U2.5.P$2 79.9,45.38 C.DEC.1.P$2 | 79.92,44.9 79.93,44.91
  Top 0.254: 72.87,35.83 U2.6 73.34,35.83 | 73.42,28.94 U2.18 73.42,30.53 73.43,30.56 | 74.68,36.89 79.91,36.89 79.92,39.2 U2.50 79.92,36.04 80.66,35.31 82.28,35.31 82.3,35.33 U2.42 87.37,35.33 87.53,35.16 | 87.53,35.16 D.DEC.U2.4.P$1 | C.T2.C.P$1 88.78,34.74 88.36,35.16 | 88.36,35.16 87.53,35.16 | 88.36,35.16 88.53,35.16 89.96,36.59 T2.2
  Top 0.27: C.DEC.1.P$2 81.48,47.81 v81.48,48.26 | 79.68,51.66 79.68,51.64 | v80.88,51.66 79.68,51.66 | 79.68,51.66 79.68,51.71 | 76.65,61.21 D3V3.P$K | 123.09,96.07 123.7,96.68 142.37,96.68 143.08,97.39 143.08,97.66 143.06,97.66 U$3.P$1
  Bottom 0.17: v89.91,52.99 90.26,53.34 v90.26,55.39 | v70.67,52.19 73.78,52.19 v73.76,52.26
  Bottom 0.2: v29.57,17.49 29.56,17.04 33.94,11.49 47.54,11.49 50.58,9.71 56.31,9.71 v57.81,11.11 | v62.23,28.14 v59.93,28.14 | v90.28,35.38 99.17,35.38 v101,37.21 | v74.08,18.86 74.18,18.96 v74.18,20.86
  Bottom 0.27: v81.48,48.26 80.88,48.26 v80.88,51.66
  pour Top (isolate 0.5): 1.75,103.92 1.75,1.87 148.5,1.87 148.5,103.73 1.75,103.73
  pour Bottom (isolate 0.5): 1.94,103.73 1.94,1.87 148.31,1.87 148.31,103.73
N$1
  Top 0.2: T1.1 79.66,49.74 79.68,49.76 79.7,49.74 R.T1.B.P$2
N$2  (via drill 0.2)
  Top 0.17: 88.51,55.89 88.53,55.91 C3.P | U1.5 91.86,58.24 v91.86,59.39 | U4.5 83.61,61.29 83.63,61.26
  Top 0.2: U4.4 85.53,61.26 v88.51,58.29 88.51,55.89 | U4.4 83.63,61.26 | B+.PP 84.99,67.42 84.56,66.99 U4.4
  Bottom 0.17: 91.66,59.19 v91.86,59.39 | v88.51,58.29 88.41,58.29 88.41,59.04 88.56,59.19
  Bottom 0.2: 88.56,59.19 91.66,59.19
N$3
  Top 0.17: R.U3.RST.P$1 93.85,49.24 R.U3.RST.P$1 | U3.P$24
  Top 0.2: U3.P$24 R.U3.RST.P$1
N$4
  Top 0.2: U2.62 73.92,44.23 74.51,44.81 74.51,47.06 65.33,47.06 65.18,46.69 65.18,47.41 65.36,47.59 65.28,47.66 X1.P$1 65.26,47.61 65.08,47.79 C.XTAL1.P$2
N$5
  Top 0.17: U4.3 84.58,58.64
  Top 0.2: C4.P$2 84.58,57.47 84.58,58.64
N$6
  Top 0.2: U2.61 74.42,43.98 74.93,44.49 74.91,49.01 67.26,56.66 65.21,56.66 | 61.89,56.71 61.88,56.71 | 61.89,56.71 C.XTAL2.P$2 | 65.21,56.66 X1.P$2 | 65.21,56.66 61.93,56.66 61.89,56.71
N$7
  Top 0.2: R3V3.P$2 79.29,61.28 79.28,61.27 79.27,61.28 D3V3.P$A
N$8
  Top 0.2: 79.44,58.81 79.45,58.82 | R1V8.P$2 79.44,58.81 | D1V8.P$A 79.41,58.78 79.44,58.81
N$9  (via drill 0.2)
  Top 0.2: U$33.P 103.62,35.99 v104.84,35.99 | U5.2 113.48,37.27 v110.99,37.27
  Bottom 0.2: v104.84,35.99 106.12,37.27 v110.99,37.27
N$10
  Top 0.2: U$36.N 117.82,39.77 117.74,39.86 U5.6
N$11
  Top 0.17: 91.83,37.54 92.33,37.54 92.36,37.56 92.38,37.56
  Top 0.2: R.T2.C.P$1 88.89,37.54 91.83,37.54
  Top 0.254: U2.41 85.77,34.83 86.18,34.41 86.18,32.94 86.48,32.65 89.86,32.65 91.56,34.03 91.63,34.04 91.56,34.11 C.T2.C.P$2 91.58,34.74 91.5,34.67 | 91.5,34.67 91.61,34.91 | T2.3 92.41,37.54 92.38,37.56 91.5,36.69 91.5,34.67
N$12
  Top 0.17: D1.1 85.76,49.01 85.73,49.04 85.38,49.04 85.38,50.32 R.T1.C.P$1
  Top 0.2: T1.3 77.31,50.69 76.42,49.8 U2.57 | C.T1.C.P 77.26,53.59 77.38,53.46 T1.3 | R.T1.C.P$1 83.53,51.46 82.76,50.69 T1.3 | D1.1 85.71,48.59
N$13
  Top 0.2: T2.1 90.23,38.51 R.T2.B.P$2
N$14
  Top 0.2: U$31.P 117.7,32.52 113.61,36.61 U5.1
N$15
  Top 0.2: U5.3 114.81,37.91 116.05,36.66 116.05,36.11 117.3,34.86 U$31.N
N$16
  Top 0.2: U$32.P 117.61,36.2 115.25,38.56 U5.4
N$17
  Top 0.2: U5.5 116.01,39.21 116.48,38.73 117.46,38.73 117.64,38.55 117.66,38.57 U$32.N
N$18
  Top 0.2: U5.14 108.84,37.91 111.79,40.86 111.79,43 113.23,44.44 T1OUT.PP
N$19
  Top 0.2: R1IN.PP 108.98,43.96 108.98,38.85 108.74,38.61 107.65,38.61 U5.13
N$R.0
  Top 0.6: Y.0.P$ 1.92,6.44 1.92,6.46 R.0.P$2
N$R.1
  Top 0.6: 1.92,12.64 | 1.92,12.64 Y.1.P$ | R.1.P$2 1.92,12.63 1.92,12.64
N$R.2
  Top 0.15: Y.2.P$ 1.89,9.42 1.91,9.41 1.92,9.42 1.92,9.47
  Top 0.6: R.2.P$2 1.92,9.47
N$R.3
  Top 0.6: 1.86,15.74 1.86,15.8 | Y.3.P$ 1.86,15.76 1.86,15.74 | R.3.P$2 1.86,15.74
N$R.4
  Top 0.6: Y.4.P$ 1.89,18.77 R.4.P$2
N$R.5
  Top 0.6: Y.5.P$ 1.86,21.94 1.86,21.93 R.5.P$2
N$R.6
  Top 0.6: Y.6.P$ 1.86,28.09 1.86,28.1 R.6.P$2
N$R.7
  Top 0.6: Y.7.P$ 1.89,25.04 R.7.P$2
N$R.8
  Top 0.6: 1.86,59.07 Y.8.P$ | R.8.P$2 1.86,59.07 | 1.86,59.07 1.86,59.09
N$R.9
  Top 0.6: Y.9.P$ 1.89,55.93 R.9.P$2
N$R.10
  Top 0.6: Y.10.P$ 1.86,65.25 1.86,65.22 R.10.P$2
N$R.11
  Top 0.6: Y.11.P$ 1.86,62.15 1.86,62.16 R.11.P$2
N$R.12
  Top 0.6: 1.92,71.44 Y.12.P$ | R.12.P$2 1.92,71.44 | 1.92,71.44 1.92,71.48
N$R.13
  Top 0.6: 1.86,68.33 Y.13.P$ | R.13.P$2 1.86,68.33 | 1.86,68.33 1.86,68.35
N$R.14
  Top 0.6: 1.92,77.67 1.92,77.68 | 1.92,77.67 Y.14.P$ | R.14.P$2 1.92,77.66 1.92,77.67
N$R.15
  Top 0.6: 1.92,74.55 | 1.92,74.55 Y.15.P$ | R.15.P$2 1.92,74.56 1.92,74.55
N$R.16
  Top 0.6: 1.89,34.26 Y.16.P$ | R.16.P$2 1.89,34.26 | 1.89,34.26
N$R.17
  Top 0.6: 1.89,31.21 Y.17.P$ | R.17.P$2 1.89,31.21 | 1.89,31.21 1.89,31.22
N$R.18
  Top 0.6: Y.18.P$ | R.18.P$2 Y.18.P$ | Y.18.P$ 1.89,40.45
N$R.19
  Top 0.6: 1.92,37.36 | 1.92,37.36 Y.19.P$ | R.19.P$2 1.92,37.36 | 1.92,37.36
N$R.20
  Top 0.6: Y.20.P$ 1.89,46.68 R.20.P$2
N$R.21
  Top 0.6: Y.21.P$ R.21.P$2
N$R.22
  Top 0.6: 1.86,49.76 1.86,49.77 Y.22.P$ | R.22.P$2 1.86,49.76 | 1.86,49.76 1.86,49.74
N$R.23
  Top 0.6: Y.23.P$ | R.23.P$2 Y.23.P$ | Y.23.P$ 1.89,52.9
N$R.24
  Top 0.6: 1.92,83.88 1.92,83.87 | 1.92,83.88 Y.24.P$ | R.24.P$2 1.92,83.89 1.92,83.88
N$R.25
  Top 0.6: 1.92,80.75 1.92,80.76 Y.25.P$ | R.25.P$2 1.92,80.75 | 1.92,80.75 1.92,80.74
N$R.26
  Top 0.6: 1.92,90.05 1.92,90.06 | 1.92,90.05 Y.26.P$ | R.26.P$2 1.92,90.04 1.92,90.05
N$R.27
  Top 0.6: 1.86,86.97 1.86,86.96 Y.27.P$ | R.27.P$2 1.86,86.97 | 1.86,86.97 1.86,87
N$R.28
  Top 0.6: 1.8,96.28 1.8,96.3 | 1.8,96.28 Y.28.P$ | R.28.P$2 1.8,96.28
N$R.29
  Top 0.6: 1.8,93.17 1.8,93.19 | 1.8,93.17 Y.29.P$ | R.29.P$2 1.8,93.16 1.8,93.17
N$R.30
  Top 0.6: Y.30.P$ 1.92,99.33 5,99.34 R.30.P$2
N$R.31
  Top 0.6: Y.31.P$ 1.92,102.46 1.92,102.45 R.31.P$2
VCC
  Top 0.17: C1.P 88.04,61.24 88.06,61.24 88.06,60.14 | 143.02,101.51 142.76,101.51 | 143.02,101.51 U$3.P$2 | 144.08,101.29 143.86,101.51 143.02,101.51
  Top 0.2: 88.06,60.14 U1.4 | C1.P 86.66,62.62 86.66,65.04 122.91,101.29 144.08,101.29

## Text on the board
Top: Vcc | GND | LEDCARD | USB.VBUS | Ev. Kit | USB.D+ | USB.D- | ver.0.1 | B+ | GND | 3V3 | B- | 3V3 | 3V3 | GND | 1V8 | 1V8 | R1IN | T1OUT | TXD | DTR | RTS | RXD
Bottom: GND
